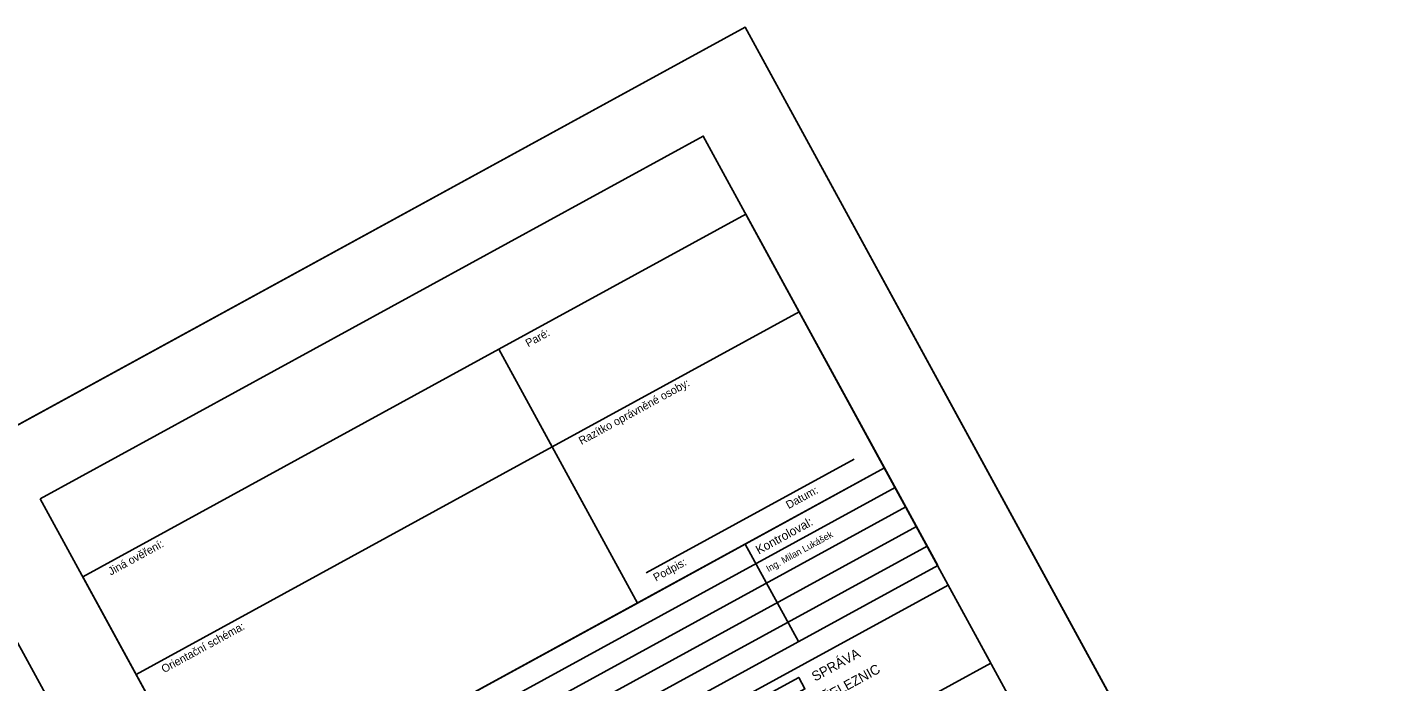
# Model space of a CAD drawing. Extents: x -9100 to -8660, y -10901 to -10569.
# Drawn here: x -8812.4 to -8660.4, y -10642.9 to -10569.3 of the extents above; entities that cross this region are included whole.
import ezdxf

# ---------------------------------------------------------------- set-up
doc = ezdxf.new("R2010")
doc.units = 0
for name, color, linetype in [('Default', 7, 'Continuous'), ('Rozpiska_Logo', 7, 'Continuous'), ('Rozpiska_pola_3', 7, 'Continuous'), ('Rozpiska_pole_1', 7, 'Continuous'), ('Rozpiska_pole_2', 7, 'Continuous'), ('Rozpiska_pole_4', 7, 'Continuous'), ('Rozpiska_pole_5', 7, 'Continuous'), ('Rozpiska_pole_6', 7, 'Continuous'), ('Rámečky-tisk', 7, 'Continuous')]:
    doc.layers.add(name, color=color, linetype=linetype)

msp = doc.modelspace()

# ---------------------------------------------------------------- linework, layer by layer
at = {"layer": 'Default'}
for p, q in [((-8731.63, -10569.34), (-8660.43, -10699.65)), ((-8743.75, -10634.07), (-8759.34, -10605.55))]:
    msp.add_line(p, q, dxfattribs=at)
at = {"layer": 'Rozpiska_Logo'}
msp.add_lwpolyline([(-8732.74, -10646.34), (-8725.59, -10642.43), (-8724.89, -10643.72), (-8732.04, -10647.63)], close=True, dxfattribs=at)
at = {"layer": 'Rozpiska_pola_3'}
msp.add_line((-8742.76, -10630.68), (-8719.35, -10617.89), dxfattribs=at)
at = {"layer": 'Rozpiska_pole_1'}
msp.add_lwpolyline([(-8810.93, -10622.34), (-8736.33, -10581.59), (-8672.81, -10697.87), (-8747.4, -10738.62)], close=True, dxfattribs=at)
at = {"layer": 'Rozpiska_pole_2'}
for points in [[(-8759.34, -10605.55), (-8731.54, -10590.36), (-8725.55, -10601.33), (-8753.34, -10616.52)], [(-8725.55, -10601.33), (-8753.34, -10616.52), (-8743.75, -10634.07), (-8715.96, -10618.89)], [(-8806.13, -10631.12), (-8759.34, -10605.55), (-8753.34, -10616.52), (-8800.14, -10642.09)], [(-8800.14, -10642.09), (-8753.34, -10616.52), (-8743.75, -10634.07), (-8790.55, -10659.64)]]:
    msp.add_lwpolyline(points, close=True, dxfattribs=at)
at = {"layer": 'Rozpiska_pole_4'}
for p, q in [((-8789.35, -10661.83), (-8714.76, -10621.08)), ((-8788.15, -10664.03), (-8713.56, -10623.27)), ((-8786.95, -10666.22), (-8712.36, -10625.47)), ((-8785.76, -10668.42), (-8711.16, -10627.66)), ((-8725.63, -10638.41), (-8731.62, -10627.44))]:
    msp.add_line(p, q, dxfattribs=at)
msp.add_lwpolyline([(-8790.55, -10659.64), (-8715.96, -10618.89), (-8709.96, -10629.86), (-8784.56, -10670.61)], close=True, dxfattribs=at)
at = {"layer": 'Rozpiska_pole_5'}
msp.add_lwpolyline([(-8783.36, -10672.8), (-8708.77, -10632.05), (-8703.97, -10640.82), (-8778.56, -10681.58)], close=True, dxfattribs=at)
at = {"layer": 'Rámečky-tisk'}
for points in [[(-9100.21, -10770.71), (-9029.01, -10901.03), (-8660.43, -10699.65), (-8731.63, -10569.34)], [(-8823.78, -10619.68), (-8752.58, -10750), (-8660.43, -10699.65), (-8731.63, -10569.34)], [(-8915.92, -10670.02), (-8844.72, -10800.34), (-8752.58, -10750), (-8823.78, -10619.68)], [(-8915.92, -10670.02), (-8844.72, -10800.34), (-8752.58, -10750), (-8823.78, -10619.68)]]:
    msp.add_lwpolyline(points, close=True, dxfattribs=at)
msp.add_lwpolyline([(-8752.58, -10750), (-8752.58, -10750), (-8823.78, -10619.68)], dxfattribs=at)

# ---------------------------------------------------------------- texts
at = {"layer": 'Rozpiska_pola_3'}
for s, p in [('Paré:', (-8756.03, -10605.34)), ('Razítko oprávněné osoby:', (-8750.04, -10616.31)), ('Datum:', (-8726.73, -10623.52)), ('Podpis:', (-8741.65, -10631.67))]:
    msp.add_text(s, height=0.9, rotation=28.6505, dxfattribs=at).set_placement(p)
at = {"layer": 'Rozpiska_pole_2'}
for s, p in [('Jiná ověření:', (-8802.98, -10630.99)), ('Orientační schéma:', (-8796.99, -10641.96))]:
    msp.add_text(s, height=0.9, rotation=28.6505, dxfattribs=at).set_placement(p)
at = {"layer": 'Rozpiska_pole_4'}
for s, height, p in [('Kontroloval:', 1, (-8730.09, -10628.63)), ('Ing. Milan Lukášek', 0.75, (-8729.01, -10630.6))]:
    msp.add_text(s, height=height, rotation=28.6505, dxfattribs=at).set_placement(p)
at = {"layer": 'Rozpiska_pole_6'}
for s, p in [('SPRÁVA', (-8723.76, -10642.91)), ('ŽELEZNIC', (-8722.51, -10645.21))]:
    msp.add_text(s, height=1.092, rotation=28.6505, dxfattribs=at).set_placement(p)

doc.saveas('drawing.dxf')
